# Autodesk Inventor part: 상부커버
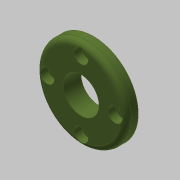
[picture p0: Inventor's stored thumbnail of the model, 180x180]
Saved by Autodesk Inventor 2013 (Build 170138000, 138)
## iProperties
Created: 2020-07
Part Number: 상부커버
Material: 알루미늄 6061
Document SubType Name: Modeling
Designer: mduedu
Density: 1 g/cm^3
Author: mduedu
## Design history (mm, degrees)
sketch "스케치1"
  geometry: L1 (0, 0)-(7, 0); L2 (7, 0)-(7, 25); L3 (7, 25)-(0, 25); L4 (0, 25)-(0, 0); L5 (7, 0)-(10, 0); L6 (10, 0)-(10, 14); L7 (10, 14)-(7, 14); L8 (7, 14)-(7, 0)
  constraints: 16 end point, 4 parallel, 2 horizontal, 2 perpendicular
  dimensions: "d0" = 50 diameter of L3 L1; "d2" = 28 diameter of L7 L5; "d3" = 7 distance of L2.end L3.end; "d4" = 10 distance between parallel lines of L6 L4
revolve "회전1" sketch "스케치1" stored, may be unused: angle "d5" = 90 deg
sketch "스케치2"
  geometry: C1 r 10 at (0, 0); 1 further point
  constraints: 1 centre point, 1 coincident
  dimensions: "d6" = 20 diameter of C1
extrude "돌출1" cut sketch "스케치2" stored distance "d7" = 10; taper "d8" = 0 deg
chamfer "모따기1" distance "d9" = 1; stored, may be unused: second distance "d10" = 2, angle "d11" = 45 deg
fillet "모깎기1" dims "d12" = 3
sketch "스케치3" dims "d13" = 38
  geometry: 3 further points
  constraints: 2 vertical alignment, 1 coincident, 2 other
hole "구멍1" sketch "스케치3" at (0, 19) diameter "d14" = 4.5; stored, may be unused: countersink angle "d18" = 90 deg, drill point angle "d20" = 118 deg; dims "d15" = 6, "d16" = 8, "d17" = 4.4, "d19" = 8
node "솔리드1"
pattern_circular "원형 패턴1" dims angle "d22" = 360 deg
